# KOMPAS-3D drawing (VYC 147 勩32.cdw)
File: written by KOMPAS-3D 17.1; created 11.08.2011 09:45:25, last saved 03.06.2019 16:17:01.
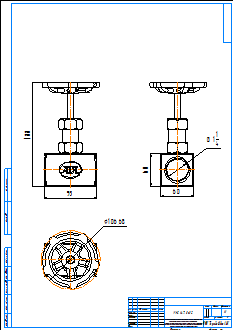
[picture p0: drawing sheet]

Sheet 1: A2, portrait

Title block, sheet 1: name: VYC 147 Ду32; material: Внимание! Данный продукт является объектом авторского права ООО «Торговый Дом АДЛ». / Запрещается изменение, копирование, распространение / (в том числе путем копирования на другие сайты и ресурсы в Интернете) / или любое иное использование информации и объектов без предварительного / согласия правообладателя (ООО «Торговый Дом АДЛ»).; scale: 1:1; sheets: 1; organisation: ООО "Торговый дом АДЛ"; sheet format: A2; stored path: \\adlc.lan\data\АДЛ_ПКД\3D-модели\Поставщики\VYC Industrial\VYC 147\KOMPAS 2D\VYC 147 Ду32.cdw

Views: Спереди 1, Проекционный вид 2, Проекционный вид 3
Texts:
  bsv
  adl
Dimensions and other numbers on the sheet: 95; 188; 60; 106,68; 1:1; 1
